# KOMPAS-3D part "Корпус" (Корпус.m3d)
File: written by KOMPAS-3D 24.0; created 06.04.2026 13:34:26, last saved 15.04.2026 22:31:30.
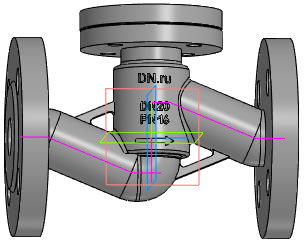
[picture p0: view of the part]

Document properties: Автор: R2D2; Полное имя файла: E:\Работа\Зайцев\VSO3131M-F-S Клапан запорный DN.ru Ду15-100 Ру16\DN20\исходные материалы\Корпус.m3d

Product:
- Body: Труба / Нестандартная труба / L = 73.6 мм  | qty 1
    Материал: Нестандартная труба (density 7856 kg/m3)
    Масса: 3.579625
    Раздел спецификации: Детали
    Примечание: 0,41 кг
    additional columns: Pipeline; 0.03; 0; 0; 0.002; 0.07364; true; 0.04
- Body: Труба / Нестандартная труба / L = 89.3 мм  | qty 1
    Материал: Нестандартная труба (density 7856 kg/m3)
    Масса: 3.579625
    Раздел спецификации: Детали
    Примечание: 0,5 кг
    additional columns: Pipeline; 0.03; 0; 0; 0.002; 0.08927; true; 0.04
- Body: Тело 4  | qty 1
    Материал: Нестандартная труба (density 7856 kg/m3)
    Масса: 3.579625
- Body: Тело 5  | qty 1
    Материал: Нестандартная труба (density 7856 kg/m3)
    Масса: 3.579625
- Part/product: Корпус
    Масса: 6.9

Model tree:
1. Труба
2. Труба:1  (labels: {F703FF30-5BE6-4673-A7F1-8EDA1BE1E2D1}; SHAPEOBJECT3D_ATTR_BUTT; SHAPEOBJECT3D_ATTR_VALID; SHAPEOBJECT3D_ATTR_BUTT_AREA)
     PIPE_R = 7
3. Труба:2  (labels: {F703FF30-5BE6-4673-A7F1-8EDA1BE1E2D1}; SHAPEOBJECT3D_ATTR_BUTT; SHAPEOBJECT3D_ATTR_VALID; SHAPEOBJECT3D_ATTR_BUTT_AREA)
     PIPE_R = 7
4. Колонна
5. Элемент выдавливания:1
     Смещение 1 = -1; Смещение 2 = -5
6. Скругление:17  (with: Ребро.Элемент выдавливания:1)
     Радиус = 1
7. Скругление:18  (with: Ребро.Элемент выдавливания:1)
8. Скругление:24  (with: Ребро.Элемент выдавливания:1)
     Радиус = 1.5
9. Элемент выдавливания:2
     Расстояние 1 = 6
10. Скругление:19  (with: Ребро.Элемент выдавливания:2)
     Радиус = 2
11. Эскиз:4  (with: Грань.Элемент выдавливания:1)
12. Элемент выдавливания:3
     Расстояние 1 = 9
13. Скругление:21  (with: Ребро.Элемент выдавливания:3)
14. ОТЛИВКА
15. Скругление:6  (with: Грань.Элемент выдавливания:1)
     Радиус = 2
16. Элемент выдавливания:6  (with: Грань.Элемент выдавливания:1)
     Смещение 1 = 4
17. ЛЕЙБЛ
18. Элемент выдавливания:7  (with: Грань.Элемент выдавливания:1)
     Расстояние 1 = 20.9931; Смещение 1 = 1
19. Фланец верх  (with: Ребро.Элемент выдавливания:3)
20. Элемент вращения:2
     Угол 1 = 360
21. Эскиз:12  (with: Грань.Элемент вращения:2)
22. Элемент выдавливания:9  (with: Грань.Элемент вращения:2)
     Расстояние 2 = 20
23. Массив по концентрической сетке:1  (with: Элемент выдавливания:9, Эскиз:12, Грань.Элемент вращения:2)  (4 pattern instances)
     Шаг 2 = 360
24. Фланец
25. Элемент вращения:1
     Угол 1 = 360
26. Эскиз:10  (with: Грань.Элемент вращения:1)
27. Элемент выдавливания:8
28. Массив по концентрической сетке:2  (with: Элемент выдавливания:8, Эскиз:10, Грань.Элемент вращения:1)  (4 pattern instances)
     Шаг 2 = 360
29. Зеркальный массив:1
30. Экземпляр ( 1 )
31. Экземпляр ( 2 )  (with: Элемент вращения:1, Массив по концентрической сетке:2, Экземпляр ( 1 ), Элемент выдавливания:8)
32. Экземпляр ( 3 )  (with: Элемент выдавливания:8)
33. Экземпляр ( 4 )  (with: Элемент выдавливания:8)

Expressions: DS/2+3; D1/2; DN/2; DS-v977*4; LL/2; D1-v1234*2; D/2-6
Referenced files in C:\Program Files\ASCON\KOMPAS-3D v24\Libs\Pipeline\: StylesTemplate.a3d, TemplateHPH, InsulationStylesTemplate.a3d, Insulation
Referenced files in C:\Program Files\ASCON\KOMPAS-3D v24\Templates\: Констр. чертеж А3 гориз. перв. лист.cdt
Referenced files in E:\Работа\Зайцев\VSO3131M-F-S Клапан запорный DN.ru Ду15-100 Ру40\DN20\исходные материалы\: 
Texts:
  Отводы ГОСТ 17375-2001
  Констр. чертеж А3 гориз. перв. лист.cdt
  GOST 26.020 Pr3
  var3D
  GOST 2.304 type A
  PN16
  смещение колонны вниз
  LL-10
  DN+10
  Труба / Нестандартная труба / L = %s мм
